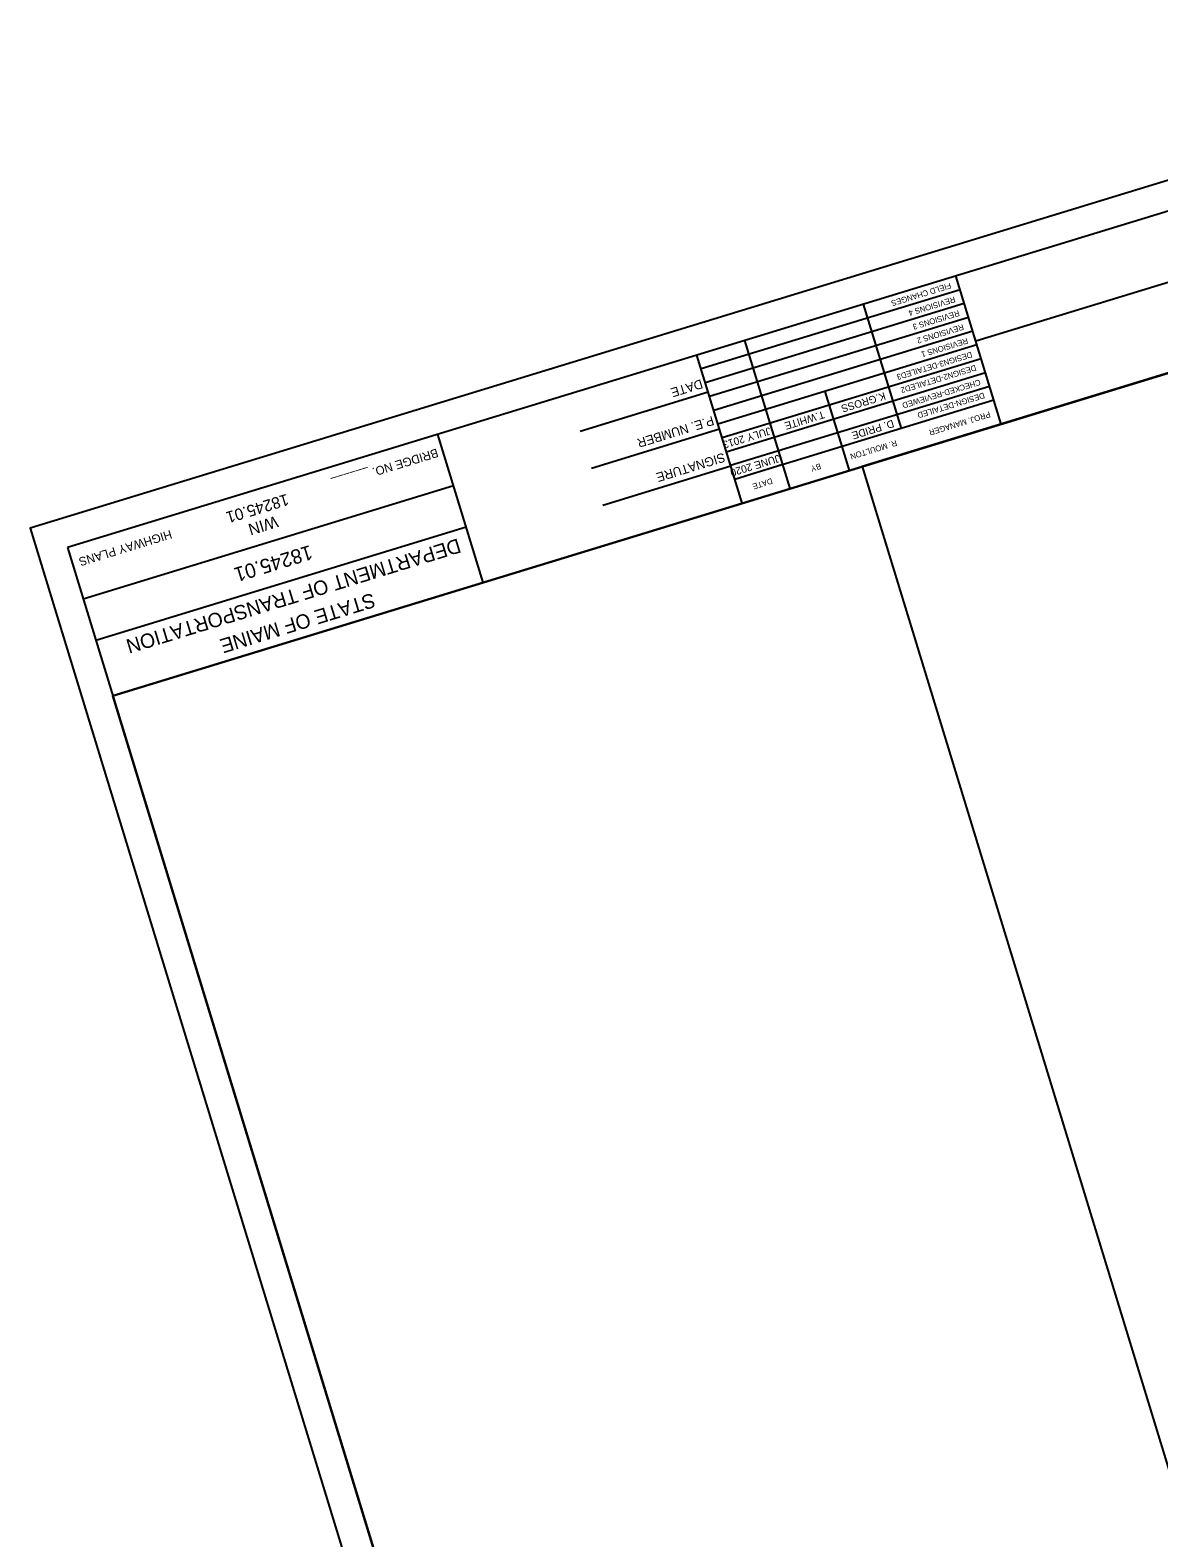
# Model space of a CAD drawing. Extents: x 1038073 to 1038848, y 778999 to 779973.
# Drawn here: x 1038073.4 to 1038437.9, y 779486.1 to 779972.9 of the extents above; entities that cross this region are included whole.
import ezdxf

# ---------------------------------------------------------------- set-up
doc = ezdxf.new("R2010")
doc.units = 0
for name, color, linetype in [('CLIPS', 7, 'Continuous'), ('Default', 7, 'Continuous'), ('PLOT BOUNDARY', 7, 'Continuous')]:
    doc.layers.add(name, color=color, linetype=linetype)

msp = doc.modelspace()

# ---------------------------------------------------------------- linework, layer by layer
at = {"layer": 'CLIPS'}
for points in [[(1038817.65, 779193.13), (1038598.37, 779910.36), (1038342.08, 779832), (1038561.36, 779114.78)], [(1038319.41, 779040.8), (1038100.13, 779758.03), (1038486.62, 779876.19), (1038705.9, 779158.97)]]:
    msp.add_lwpolyline(points, close=True, dxfattribs=at)
at = {"layer": 'Default'}
for p, q in [((1038587.55, 779959.34), (1038085.5, 779805.84)), ((1038546.18, 779923.64), (1038378.83, 779872.47)), ((1038602.17, 779911.52), (1038100.11, 779758.03)), ((1038387, 779845.74), (1038372.39, 779893.55)), ((1038303.33, 779820.16), (1038288.71, 779867.97)), ((1038292.36, 779856.02), (1038251.02, 779843.38)), ((1038219.69, 779794.59), (1038205.08, 779842.4)), ((1038296.02, 779844.06), (1038254.67, 779831.42)), ((1038299.67, 779832.11), (1038258.33, 779819.47)), ((1038210.14, 779825.78), (1038090.61, 779789.23)), ((1038214.23, 779812.41), (1038094.69, 779775.86)), ((1038085.51, 779805.85), (1038319.41, 779040.8))]:
    msp.add_line(p, q, dxfattribs=at)
for points in [[(1038373.73, 779889.1), (1038290.07, 779863.52)], [(1038375.09, 779884.64), (1038291.43, 779859.07)], [(1038354.76, 779844.32), (1038342.5, 779884.42)], [(1038376.46, 779880.19), (1038292.79, 779854.61)], [(1038377.82, 779875.73), (1038294.16, 779850.16)], [(1038379.18, 779871.28), (1038295.52, 779845.7)], [(1038318.87, 779824.91), (1038304.25, 779872.72)], [(1038380.54, 779866.82), (1038296.88, 779841.25)], [(1038298.24, 779836.79), (1038381.9, 779862.37)], [(1038383.27, 779857.91), (1038299.6, 779832.34)], [(1038335.63, 779838.48), (1038330.19, 779856.3)], [(1038384.63, 779853.46), (1038304.34, 779828.91)], [(1038337.99, 779830.75), (1038335.63, 779838.48)], [(1038316.51, 779832.63), (1038300.97, 779827.88)]]:
    msp.add_lwpolyline(points, dxfattribs=at)
at = {"layer": 'PLOT BOUNDARY'}
msp.add_lwpolyline([(1038847.92, 779160.07), (1038599.41, 779972.93), (1038073.44, 779812.13), (1038321.96, 778999.27)], close=True, dxfattribs=at)

# ---------------------------------------------------------------- texts
at = {"layer": 'Default'}
for s, height, p in [('FIELD CHANGES', 1.8637, (1038370.49, 779891.42)), ('REVISIONS 4', 1.8637, (1038371.85, 779886.96)), ('REVISIONS 3', 1.8637, (1038373.21, 779882.51)), ('REVISIONS 2', 1.8637, (1038374.57, 779878.05)), ('DESIGN3-DETAILED3', 1.8637, (1038377.3, 779869.14)), ('REVISIONS 1', 1.8637, (1038375.93, 779873.6)), ('DESIGN2-DETAILED2', 1.8637, (1038378.6, 779864.87)), ('DATE', 2.953, (1038290.07, 779860.24)), ('CHECKED-REVIEWED', 1.8637, (1038380.02, 779860.24)), ('K.GROSS', 2.423, (1038349.22, 779856.07)), ('DESIGN-DETAILED', 1.8637, (1038381.33, 779855.96)), ('T.WHITE', 2.423, (1038329.55, 779850.06)), ('PROJ. MANAGER', 1.8637, (1038383.2, 779849.83)), ('P.E. NUMBER', 2.9528, (1038293.7, 779848.38)), ('JULY 2013', 2.423, (1038312.17, 779844.75)), ('D. PRIDE', 2.423, (1038351.94, 779847.16)), ('R. MOULTON', 1.864, (1038353.01, 779840.6)), ('BRIDGE NO. ______', 2.795, (1038204.7, 779837.89)), ('SIGNATURE', 2.953, (1038297.32, 779836.52)), ('JUNE 2020', 2.423, (1038315.11, 779835.9)), ('BY', 1.857, (1038328.47, 779833.09)), ('DATE', 1.857, (1038312.83, 779828.31)), ('18245.01', 3.726, (1038156.26, 779823.27)), ('WIN', 3.726, (1038152.79, 779816.15)), ('HIGHWAY PLANS', 2.795, (1038118.7, 779811.59)), ('DEPARTMENT OF TRANSPORTATION', 4.6588, (1038211.6, 779808.88)), ('18245.01', 4.659, (1038163.75, 779806.72)), ('STATE OF MAINE', 4.6588, (1038184.01, 779791.29))]:
    msp.add_text(s, height=height, rotation=197, dxfattribs=at).set_placement(p)

doc.saveas('drawing.dxf')
